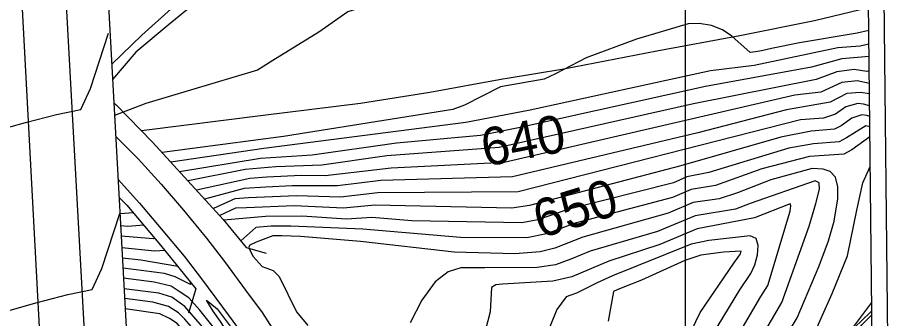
# Model space of a CAD drawing. Extents: x 79600 to 91800, y 75600 to 84400.
# Drawn here: x 86346.4 to 86808.2, y 80110.5 to 80269.9 of the extents above; entities that cross this region are included whole.
import ezdxf

# ---------------------------------------------------------------- set-up
doc = ezdxf.new("R2010")
doc.units = 0
for name, color, linetype in [('080-085$0$TI_BORDER', 7, 'Continuous'), ('084-085$0$TI_BORDER', 7, 'Continuous'), ('084-090$0$BRIDGE', 7, 'Continuous'), ('084-090$0$INDEX', 7, 'Continuous'), ('084-090$0$INDXLBL', 7, 'Continuous'), ('084-090$0$INTER', 7, 'Continuous'), ('084-090$0$INTERSTATE', 7, 'Continuous'), ('084-090$0$ROAD', 7, 'Continuous')]:
    doc.layers.add(name, color=color, linetype=linetype)

msp = doc.modelspace()

# ---------------------------------------------------------------- linework, layer by layer
at = {"layer": '080-085$0$TI_BORDER'}
msp.add_lwpolyline([(79700, 80300), (86700, 80300), (86700, 75700), (79700, 75700)], close=True, dxfattribs=at)
at = {"layer": '084-085$0$TI_BORDER'}
msp.add_lwpolyline([(79700, 84300), (86700, 84300), (86700, 79700), (79700, 79700)], close=True, dxfattribs=at)
at = {"layer": '084-090$0$BRIDGE'}
for points in [[(86386.87, 80549.67), (86380.17, 80539.57), (86409.79, 80000)], [(86800.06, 80000), (86794.2, 80539.6), (86787.02, 80545.42)], [(86713.58, 80423.73), (86703.69, 80426.68), (86683.06, 80418.67), (86660.1, 80408.95), (86647.52, 80403.7), (86627.67, 80395.04), (86612.11, 80387.18), (86600.92, 80381.32), (86598.62, 80380.11), (86574.66, 80366.96), (86548.46, 80351.34), (86528.05, 80339.56), (86509.94, 80327.8), (86491.85, 80315.73), (86464.1, 80295.85), (86445.55, 80281.93), (86426.11, 80265.83), (86409.11, 80251.46), (86396.78, 80237.01)], [(86397.45, 80224.76), (86398.58, 80223.72), (86417.92, 80203.84), (86455.38, 80162.99), (86467.41, 80148.13), (86478.09, 80145.15)], [(86400.2, 80174.68), (86404.35, 80170.52), (86422.16, 80149.39), (86440.76, 80126.26), (86437.03, 80113.41)]]:
    msp.add_lwpolyline(points, dxfattribs=at)
at = {"layer": '084-090$0$INDEX'}
for points in [[(86797.44, 80241.61), (86796.17, 80241.38), (86789.42, 80242.38), (86780.24, 80241.2), (86769.35, 80237.02), (86704.47, 80224.21), (86601.46, 80201.06), (86541.91, 80196.68), (86507.48, 80191.7), (86483.28, 80190.82), (86467.03, 80189.41), (86436.71, 80183.35)], [(86797.76, 80211.92), (86795.71, 80212.51), (86785.38, 80206.11), (86781.53, 80204.14), (86767.96, 80203.03), (86754.83, 80200.71), (86712.44, 80187.76), (86700.93, 80185.46), (86693.72, 80182.31), (86637.89, 80168.29), (86622, 80162.86), (86613.41, 80161.18), (86555.27, 80162.23), (86534.03, 80164.02), (86520.62, 80163.11), (86497.02, 80164.69), (86477.76, 80164.45), (86455.67, 80162.62)], [(86666.27, 80000), (86677.52, 80021.42), (86687.29, 80044.71), (86700.31, 80069.37), (86708.4, 80088.73), (86714.41, 80101.9), (86728.98, 80125.63), (86734.79, 80134.38), (86736.9, 80138.97), (86738.35, 80144.23), (86738.69, 80149.21), (86737.49, 80152.81), (86734.45, 80154.24), (86712.51, 80151.89), (86703.19, 80149.95), (86661.51, 80133.17), (86653.42, 80129.45), (86642.48, 80123.94), (86639.47, 80122.98), (86636.94, 80121.95), (86632.06, 80115.33), (86603.17, 80044.23), (86588.74, 80000)], [(86431.23, 80138.11), (86411.69, 80141.36), (86401.97, 80142.45)], [(86495.48, 80000), (86482.38, 80030.14), (86474.95, 80044.82), (86448.65, 80084.88), (86438.92, 80098.67), (86430.95, 80107.83), (86426.87, 80110.58), (86421.71, 80113.03), (86403.44, 80115.63)]]:
    msp.add_lwpolyline(points, dxfattribs=at)
at = {"layer": '084-090$0$INTER'}
msp.add_line((86407.69, 80166.55), (86400.68, 80165.98), dxfattribs=at)
for points in [[(86485.09, 80310.89), (86496.7, 80312.06), (86638.32, 80332.43), (86647.89, 80334), (86650.78, 80334.3), (86648.41, 80331.38), (86620.62, 80313.34), (86608.82, 80305.9), (86591.44, 80297.13), (86570.9, 80287.26), (86564.64, 80284.23), (86526.95, 80274.73), (86521.28, 80272.97), (86506.04, 80262.21), (86481.58, 80247.05), (86473.41, 80242.09), (86414.27, 80224.43), (86397.82, 80218.03)], [(86797.2, 80263.03), (86791.13, 80261.59), (86760.57, 80256.46), (86745.75, 80253.43), (86740.32, 80252.3), (86737.17, 80251.64), (86734.39, 80251.35), (86724.73, 80260.08), (86719.83, 80263.35), (86713.85, 80265.58), (86707.46, 80266.64), (86701.51, 80266.59), (86674.13, 80258.5), (86647.58, 80248.47), (86631.32, 80240), (86625.3, 80237.26), (86602.19, 80233.27), (86583.13, 80223.47), (86577.02, 80221.17), (86487.23, 80206.93), (86422.97, 80198.34)], [(86287.13, 80256.38), (86293.15, 80210), (86309.47, 80208.29), (86335.24, 80210), (86350.71, 80214.3), (86367.03, 80218.59), (86379.92, 80221.17), (86385.07, 80232.33), (86394.52, 80261.53)], [(86797.28, 80255.75), (86792.72, 80254.75), (86780.91, 80253.84), (86736.52, 80244.52), (86713.46, 80241.72), (86617.89, 80220.91), (86583.78, 80214.25), (86476.83, 80200.51), (86427.52, 80193.37)], [(86797.35, 80249.25), (86783.02, 80247.94), (86766.91, 80243.59), (86710.75, 80233.3), (86612.61, 80211.63), (86591.53, 80207.43), (86547.02, 80203.4), (86502.42, 80196.97), (86475.12, 80195.28), (86432.21, 80188.25)], [(86797.51, 80234.97), (86791.1, 80236.28), (86782.91, 80235.39), (86771.79, 80230.44), (86758.08, 80228.73), (86604.06, 80193.12), (86544.27, 80190.1), (86509.39, 80185.98), (86496.8, 80186.2), (86478.43, 80185.37), (86469.34, 80184.68), (86441.16, 80178.5)], [(86797.57, 80229.55), (86792.77, 80230.19), (86785.58, 80229.58), (86776.72, 80225.13), (86753.68, 80221.01), (86706.76, 80208.8), (86608.55, 80185.55), (86538.76, 80183.61), (86515.77, 80180.7), (86491.92, 80180.8), (86477.84, 80180.15), (86466.45, 80179.38), (86445.49, 80173.77)], [(86797.64, 80223.15), (86794.45, 80224.09), (86791.48, 80224.32), (86785.12, 80222.52), (86779.61, 80218.79), (86773.2, 80216.58), (86761.07, 80215.73), (86611.48, 80177.53), (86537.18, 80177.08), (86517.39, 80174.84), (86494.18, 80175.5), (86468.73, 80174.46), (86461.52, 80173.83), (86450.13, 80168.71)], [(86797.7, 80217.48), (86796.13, 80218), (86793.59, 80218.42), (86788.19, 80216.67), (86782.5, 80212.45), (86779.1, 80210.71), (86766.65, 80209.63), (86750.68, 80206.51), (86697.68, 80191.28), (86617.52, 80170.43), (86608.13, 80168.88), (86535.6, 80170.55), (86519, 80168.98), (86492.87, 80170.15), (86467.61, 80169.2), (86461.83, 80168.88), (86453.52, 80165.02)], [(86797.82, 80206.67), (86797.72, 80206.71), (86788.27, 80199.78), (86783.97, 80197.56), (86765.9, 80196.33), (86740.51, 80189.78), (86716.07, 80180.98), (86703.17, 80178.84), (86693.22, 80174.64), (86641.79, 80160.94), (86626.49, 80155.3), (86616.14, 80153.27), (86580.94, 80153.45), (86529.35, 80157.79), (86491.17, 80159.5), (86480.56, 80159.38), (86472.53, 80158.76), (86464.62, 80151.59)], [(86742.06, 80082.3), (86759.23, 80110.85), (86770.98, 80138.49), (86775.82, 80151.58), (86778.95, 80162.14), (86780.78, 80173.94), (86780.84, 80180.28), (86779.6, 80185.37), (86776.75, 80188.33), (86773.08, 80189.59), (86767.25, 80189.88), (86745.39, 80183.92), (86727.63, 80177.1), (86717.9, 80173.88), (86704.2, 80171.9), (86690.99, 80166.33), (86645.7, 80153.6), (86630.97, 80147.73), (86623.2, 80145.88), (86609.71, 80144.8), (86577.71, 80145.57), (86528.03, 80151.38), (86496.26, 80153.96), (86486.32, 80154.29), (86481.6, 80154.26), (86472.83, 80150.88), (86469.43, 80149.39), (86468.73, 80148.12), (86471.19, 80143.28), (86475.93, 80138.15), (86481.83, 80136.03), (86485, 80132.86), (86494.11, 80113.99), (86500.07, 80106.82)], [(86798.82, 80114.56), (86792.86, 80108.77), (86788.47, 80104.71), (86774.86, 80099.38), (86770.95, 80097.97), (86767.8, 80097.2), (86766.09, 80097.72), (86777.78, 80123.69), (86785.99, 80143.71), (86790.89, 80167.92), (86794.02, 80182.39), (86797.99, 80191.08)], [(86730.43, 80083.71), (86751.24, 80118.94), (86765.66, 80159.45), (86769.22, 80171.37), (86771.08, 80179.06), (86771.02, 80182.43), (86768.75, 80183.46), (86734.45, 80171.45), (86726.61, 80168.5), (86705.24, 80164.96), (86685.26, 80156.57), (86649.61, 80146.25), (86639.34, 80141.87), (86631.22, 80138.92), (86621.61, 80137.46), (86593.83, 80137.28), (86581.17, 80137.3), (86574.48, 80135.31), (86567.56, 80129.95), (86560.57, 80120.33), (86554.36, 80108.32)], [(86678.06, 80000), (86720.7, 80089.03), (86740.03, 80122.11), (86743.75, 80127.97), (86755.55, 80167.4), (86756.02, 80170.18), (86755.5, 80171.17), (86736.71, 80163.86), (86706.27, 80158.02), (86686.54, 80149.69), (86659.56, 80140.91), (86639.94, 80132.6), (86629.93, 80130.22), (86603.28, 80128.69), (86599.77, 80128.33), (86597.48, 80127.03), (86596.65, 80114.15), (86581.28, 80054.97), (86576.48, 80035.53), (86575.03, 80026.92), (86578.97, 80000)], [(86293.15, 80161.05), (86299.16, 80114.68), (86315.48, 80112.96), (86341.26, 80114.68), (86356.72, 80118.97), (86373.05, 80123.27), (86385.93, 80125.84), (86391.09, 80137.01), (86400.54, 80166.21)], [(86413.3, 80159.9), (86404.8, 80159.2), (86401.03, 80159.53)], [(86419.09, 80153.02), (86418.19, 80152.66), (86401.33, 80154.14)], [(86424.42, 80146.57), (86419.15, 80146.13), (86401.67, 80148)], [(86701.26, 80099.69), (86707.95, 80113.75), (86725.72, 80139.86), (86727.96, 80142.94), (86729.23, 80144.86), (86729.65, 80146.17), (86720.21, 80145.62), (86708.35, 80144.14), (86699.74, 80141.23), (86676.8, 80130.83), (86667.9, 80127.25), (86663.94, 80125.78), (86662.07, 80124.75), (86659.25, 80109.15)], [(86437.76, 80129.99), (86437.96, 80128.5), (86429.82, 80132.64), (86424.21, 80134.43), (86402.27, 80137.12)], [(86509.39, 80000), (86496.75, 80028.34), (86485.24, 80051.25), (86463.01, 80086.8), (86451.45, 80104.28), (86442.97, 80115.02), (86437.11, 80121.46), (86431.99, 80124.92), (86427.8, 80127.74), (86418.79, 80129.84), (86402.56, 80131.82)], [(86504.75, 80000), (86491.46, 80030), (86481.31, 80049.96), (86455.78, 80090.04), (86444.39, 80106.19), (86435.06, 80116.92), (86428.05, 80121.78), (86421.23, 80124), (86402.86, 80126.32)], [(86500.12, 80000), (86487.39, 80028.98), (86478.83, 80046.12), (86448.91, 80092.51), (86441.66, 80102.43), (86435.08, 80110.23), (86431.62, 80113.56), (86426.43, 80116.89), (86417.98, 80119.19), (86403.15, 80121.04)], [(86749.16, 80000), (86758.53, 80017.72), (86769.13, 80051.87), (86779.46, 80074.6), (86783.93, 80087.67), (86788.09, 80098.66), (86793.61, 80107.12), (86798.84, 80112.44)]]:
    msp.add_lwpolyline(points, dxfattribs=at)
msp.add_lwpolyline([(86470.12, 80090.99), (86478.34, 80075.81), (86481.62, 80069.43), (86482.96, 80066.2), (86484.12, 80063.02), (86484.39, 80061.48), (86453.92, 80108.91), (86450.05, 80114.34), (86447.98, 80117.58), (86446.49, 80120.3), (86452.11, 80115.68), (86466.47, 80096.64)], close=True, dxfattribs=at)
at = {"layer": '084-090$0$INTERSTATE'}
for points in [[(86388.06, 80000), (86385.79, 80033.24), (86360.4, 80494.29), (86345.92, 80771.43), (86336, 80963.54), (86326.86, 81137.91), (86320.52, 81263.67), (86318.07, 81324.48), (86315.73, 81420.48), (86315.85, 81502.31), (86316.71, 81571.79), (86318.48, 81626.61), (86320.82, 81671.41), (86324.57, 81729.19), (86329.36, 81790.68), (86335.5, 81856.97), (86343.16, 81925.6), (86353.39, 81999.49), (86361.62, 82057.01), (86376.21, 82142.68), (86391.47, 82215.41)], [(86320.99, 80792.25), (86327.38, 80676.92), (86340.26, 80436.46), (86363.56, 80000.16)], [(86600.67, 80388.82), (86599.37, 80388.17), (86584.1, 80379.1), (86569.73, 80370.54), (86555.15, 80362.36), (86541.33, 80354.35), (86527.21, 80345.88), (86514.32, 80338.03), (86497.45, 80326.59), (86485.8, 80318.61), (86465.1, 80303.58), (86446.72, 80289.19), (86428.03, 80274.65), (86412.26, 80260.6), (86396.34, 80245.12)], [(86605.71, 80237.81), (86635.71, 80242.64), (86684.92, 80252.2), (86728.94, 80260.44), (86768.42, 80268.27), (86797.07, 80275.11)], [(86411.8, 80210.13), (86413.53, 80210.28), (86476.44, 80218.16), (86527.95, 80224.54), (86564.79, 80230.3), (86603.37, 80237.43), (86605.71, 80237.81)], [(86398.43, 80206.89), (86410.3, 80195.05), (86422.43, 80181.73), (86434.23, 80167.83), (86446.48, 80153.01), (86455.96, 80140.73), (86467.18, 80125.56), (86475.93, 80113.66), (86484.1, 80100.93), (86490.76, 80089.17), (86497.74, 80077.93), (86504.6, 80066.32), (86511.88, 80051.16), (86519.77, 80033.9), (86526.52, 80017.83), (86532.51, 80003.49), (86533.77, 80000)], [(86399.69, 80184.06), (86410.98, 80171.66), (86422.54, 80158.04), (86434.57, 80143.49), (86443.8, 80131.54), (86454.91, 80116.52), (86463.36, 80105.02), (86471.04, 80093.05), (86477.64, 80081.39), (86484.7, 80070.03), (86491.14, 80059.13), (86498.08, 80044.69), (86505.81, 80027.78), (86512.45, 80011.95), (86517.44, 80000)], [(86712.18, 80000), (86716.09, 80006.57), (86725.13, 80020.78), (86736.37, 80036.94), (86752.91, 80059.23), (86763.89, 80073.83), (86777.73, 80090.78), (86798.77, 80119.08)]]:
    msp.add_lwpolyline(points, dxfattribs=at)
at = {"layer": '084-090$0$ROAD'}
msp.add_line((86802.06, 80555.35), (86808.21, 80000), dxfattribs=at)

# ---------------------------------------------------------------- texts
at = {"layer": '084-090$0$INDXLBL'}
for s, rotation, p in [('640', 10.9498, (86594.08, 80190.82)), ('650', 17.0963, (86623.33, 80152.85))]:
    msp.add_text(s, height=20, rotation=rotation, dxfattribs=at).set_placement(p)

doc.saveas('drawing.dxf')
